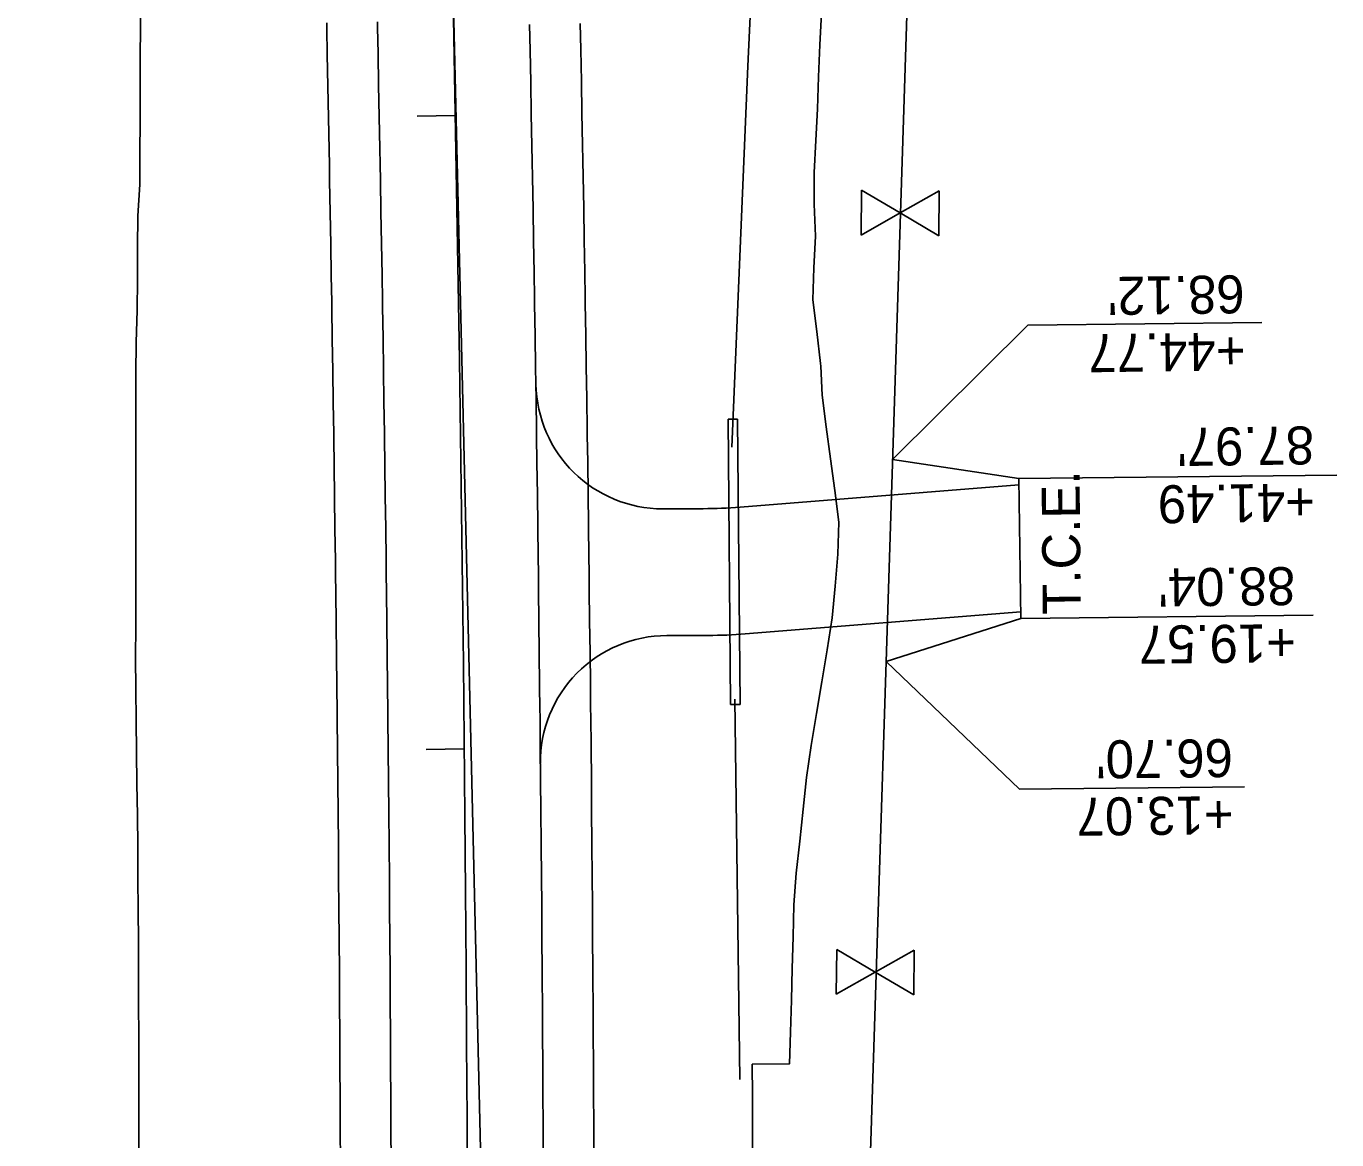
# Model space of a CAD drawing. Extents: x 634057 to 641016, y 287858 to 292331.
# Drawn here: x 634256.5 to 634463.2, y 290902.9 to 291078.6 of the extents above; entities that cross this region are included whole.
import ezdxf

# ---------------------------------------------------------------- set-up
doc = ezdxf.new("R2010")
doc.units = 0
for name, color, linetype in [('53', 7, 'Continuous'), ('PROPOSED SPECIAL DITCHES', 7, 'Continuous'), ('R_50 Horz Alg PC PI PT', 7, 'Continuous'), ('R_50 Horz Alg Ticks', 7, 'Continuous'), ('R_Drive', 7, 'Continuous'), ('R_Horz Alg', 7, 'Continuous'), ('R_Proposed Const Limits', 7, 'Continuous'), ('R_Proposed Road', 7, 'Continuous'), ('R_Proposed Shoulder', 7, 'Continuous'), ('R_ROW', 7, 'Continuous'), ('R_Water', 7, 'Continuous')]:
    doc.layers.add(name, color=color, linetype=linetype)

msp = doc.modelspace()

# ---------------------------------------------------------------- linework, layer by layer
at = {"layer": '53'}
for p, q in [((634463.23, 291007.76), (634413.05, 291007.22)), ((634459.5, 290985.67), (634413.39, 290985.14))]:
    msp.add_line(p, q, dxfattribs=at)
for points in [[(634414.48, 291031.42), (634393.15, 291010.25)], [(634451.39, 291031.86), (634414.5, 291031.42)], [(634392.13, 290978.35), (634413.15, 290958.19)], [(634413.15, 290958.19), (634448.69, 290958.58)]]:
    msp.add_lwpolyline(points, dxfattribs=at)
at = {"layer": 'PROPOSED SPECIAL DITCHES'}
for points in [[(634367.76, 291012.19), (634370.29, 291072.3), (634378.27, 291242.02), (634381.78, 291263.48)], [(634369.03, 290912.39), (634368.25, 290972.39)]]:
    msp.add_lwpolyline(points, dxfattribs=at)
at = {"layer": 'R_50 Horz Alg PC PI PT'}
msp.add_lwpolyline([(634341.05, 290353.77), (634322.94, 291121.85)], dxfattribs=at)
at = {"layer": 'R_50 Horz Alg Ticks'}
for points in [[(634318.15, 291064.43), (634324.15, 291064.54)], [(634319.57, 290964.49), (634325.57, 290964.55)]]:
    msp.add_lwpolyline(points, dxfattribs=at)
at = {"layer": 'R_Drive'}
for p, q in [((634369.09, 291002.71), (634413.06, 291006.24)), ((634356.93, 291002.45), (634363.26, 291002.47)), ((634369.91, 290982.71), (634413.38, 290986.2)), ((634357.53, 290982.45), (634364.09, 290982.47))]:
    msp.add_line(p, q, dxfattribs=at)
for centre, radius, start, end in [((634356.88, 291022.45), 20, 180.8408, 270.1318), ((634363.09, 291077.47), 75, 270.1318, 274.5873), ((634357.58, 290962.45), 20, 90.1318, 180.5616), ((634363.91, 291057.47), 75, 270.1318, 274.5873)]:
    msp.add_arc(centre, radius, start, end, dxfattribs=at)
at = {"layer": 'R_Horz Alg'}
msp.add_arc((622866.97, 290851.82), 11459.16, 353.678846, 1.350269, dxfattribs=at)
at = {"layer": 'R_Proposed Const Limits'}
for points in [[(634274.25, 290899.34), (634274.24, 290904.31), (634274.24, 290909.29), (634274.22, 290914.26), (634274.22, 290914.27), (634274.2, 290919.25), (634274.19, 290924.22), (634274.18, 290929.2), (634274.15, 290934.18), (634274.11, 290939.16), (634274.07, 290944.13), (634274.05, 290949.11), (634273.99, 290954.09), (634273.93, 290959.06), (634273.87, 290964.04), (634273.81, 290969.02), (634273.74, 290974), (634273.72, 290978.97), (634273.73, 290983.95), (634273.75, 290988.93), (634273.75, 290993.91), (634273.75, 290998.89), (634273.76, 291003.86), (634273.77, 291008.84), (634273.77, 291013.82), (634273.75, 291018.8), (634273.76, 291023.37), (634273.77, 291023.78), (634273.78, 291028.75), (634273.97, 291033.74), (634274, 291038.72), (634274.02, 291043.69), (634274.05, 291048.67), (634274.36, 291053.66), (634274.4, 291058.64), (634274.44, 291063.62), (634274.44, 291068.6), (634274.45, 291073.58), (634274.48, 291078.56), (634274.5, 291083.54)], [(634381.93, 291080.69), (634381.69, 291075.66), (634381.45, 291070.63), (634381.29, 291065.6), (634381.04, 291060.57), (634380.8, 291055.54), (634380.75, 291050.51), (634380.98, 291045.49), (634380.71, 291040.46), (634380.57, 291035.44), (634381.22, 291030.42), (634381.78, 291025.4), (634381.81, 291024.99), (634382.02, 291020.38), (634382.69, 291015.37), (634383.36, 291010.35), (634384.02, 291005.33), (634384.67, 291000.32), (634384.52, 290995.29), (634384.1, 290990.26), (634383.64, 290985.22), (634382.81, 290980.19), (634381.98, 290975.16), (634381.14, 290970.12), (634380.3, 290965.09), (634379.56, 290960.06), (634379.04, 290955.03), (634378.5, 290950), (634377.91, 290944.97), (634377.58, 290939.95), (634377.45, 290934.92), (634377.32, 290929.9), (634377.18, 290924.88), (634377.03, 290919.85), (634376.88, 290914.83), (634371.01, 290914.79)], [(634371.01, 290914.79), (634371.02, 290909.78), (634371.03, 290904.76), (634371.05, 290899.74)]]:
    msp.add_lwpolyline(points, dxfattribs=at)
at = {"layer": 'R_Proposed Road'}
for points in [[(634314.02, 290899.5), (634314, 290904.5), (634314, 290905.72), (634313.98, 290909.49), (634313.95, 290914.49), (634313.92, 290919.48), (634313.89, 290924.48), (634313.87, 290927.31), (634313.86, 290929.47), (634313.82, 290934.46), (634313.79, 290939.46), (634313.75, 290944.45), (634313.71, 290948.89), (634313.71, 290949.45), (634313.66, 290954.44), (634313.62, 290959.44), (634313.57, 290964.43), (634313.52, 290969.43), (634313.51, 290970.48), (634313.47, 290974.42), (634313.41, 290979.42), (634313.36, 290984.41), (634313.3, 290989.4), (634313.26, 290992.07), (634313.23, 290994.4), (634313.17, 290999.39), (634313.11, 291004.39), (634313.04, 291009.38), (634312.98, 291013.65), (634312.97, 291014.38), (634312.9, 291019.37), (634312.82, 291024.36), (634312.75, 291029.36), (634312.67, 291034.35), (634312.65, 291035.23), (634312.59, 291039.35), (634312.5, 291044.34), (634312.42, 291049.34), (634312.33, 291054.33), (634312.29, 291056.82), (634312.24, 291059.32), (634312.15, 291064.32), (634312.06, 291069.31), (634311.96, 291074.31), (634311.88, 291078.4), (634311.86, 291079.3)], [(634338.02, 290899.6), (634338, 290904.61), (634338, 290905.83), (634337.98, 290909.61), (634337.95, 290914.62), (634337.92, 290919.62), (634337.89, 290924.63), (634337.87, 290927.47), (634337.86, 290929.63), (634337.82, 290934.64), (634337.79, 290939.64), (634337.75, 290944.65), (634337.71, 290949.1), (634337.71, 290949.65), (634337.66, 290954.66), (634337.62, 290959.66), (634337.57, 290964.67), (634337.52, 290969.67), (634337.51, 290970.73), (634337.46, 290974.68), (634337.41, 290979.68), (634337.35, 290984.69), (634337.29, 290989.69), (634337.26, 290992.36), (634337.23, 290994.7), (634337.17, 290999.7), (634337.1, 291004.71), (634337.04, 291009.71), (634336.98, 291013.99), (634336.97, 291014.72), (634336.89, 291019.72), (634336.82, 291024.73), (634336.74, 291029.73), (634336.66, 291034.74), (634336.65, 291035.62), (634336.58, 291039.74), (634336.5, 291044.75), (634336.42, 291049.75), (634336.33, 291054.75), (634336.28, 291057.25), (634336.24, 291059.76), (634336.15, 291064.76), (634336.05, 291069.77), (634335.96, 291074.77), (634335.88, 291078.88)]]:
    msp.add_lwpolyline(points, dxfattribs=at)
at = {"layer": 'R_Proposed Shoulder'}
for points in [[(634306.02, 290899.47), (634306, 290904.46), (634306, 290905.68), (634305.98, 290909.45), (634305.95, 290914.44), (634305.92, 290919.43), (634305.89, 290924.42), (634305.87, 290927.25), (634305.86, 290929.42), (634305.82, 290934.41), (634305.79, 290939.4), (634305.75, 290944.39), (634305.71, 290948.83), (634305.71, 290949.38), (634305.66, 290954.37), (634305.62, 290959.36), (634305.57, 290964.35), (634305.52, 290969.34), (634305.51, 290970.4), (634305.47, 290974.34), (634305.41, 290979.33), (634305.36, 290984.32), (634305.3, 290989.31), (634305.26, 290991.97), (634305.24, 290994.3), (634305.17, 290999.29), (634305.11, 291004.28), (634305.04, 291009.27), (634304.98, 291013.54), (634304.97, 291014.26), (634304.9, 291019.25), (634304.82, 291024.24), (634304.75, 291029.24), (634304.67, 291034.23), (634304.65, 291035.11), (634304.59, 291039.22), (634304.51, 291044.21), (634304.42, 291049.2), (634304.33, 291054.19), (634304.29, 291056.68), (634304.24, 291059.18), (634304.15, 291064.17), (634304.06, 291069.16), (634303.96, 291074.15), (634303.88, 291078.24), (634303.86, 291079.14)], [(634346.02, 290899.64), (634346, 290904.64), (634346, 290905.87), (634345.98, 290909.65), (634345.95, 290914.66), (634345.92, 290919.67), (634345.89, 290924.68), (634345.87, 290927.52), (634345.86, 290929.69), (634345.82, 290934.7), (634345.79, 290939.7), (634345.75, 290944.71), (634345.71, 290949.16), (634345.71, 290949.72), (634345.66, 290954.73), (634345.62, 290959.74), (634345.57, 290964.75), (634345.52, 290969.76), (634345.51, 290970.81), (634345.46, 290974.76), (634345.41, 290979.77), (634345.35, 290984.78), (634345.29, 290989.79), (634345.26, 290992.46), (634345.23, 290994.8), (634345.17, 290999.81), (634345.1, 291004.81), (634345.04, 291009.82), (634344.98, 291014.1), (634344.97, 291014.83), (634344.89, 291019.84), (634344.82, 291024.85), (634344.74, 291029.86), (634344.66, 291034.86), (634344.65, 291035.75), (634344.58, 291039.87), (634344.5, 291044.88), (634344.41, 291049.89), (634344.33, 291054.9), (634344.28, 291057.39), (634344.24, 291059.9), (634344.14, 291064.91), (634344.05, 291069.92), (634343.95, 291074.93), (634343.87, 291079.04)]]:
    msp.add_lwpolyline(points, dxfattribs=at)
at = {"layer": 'R_ROW'}
for p, q in [((634388.2, 291045.66), (634388.26, 291052.73)), ((634388.26, 291052.73), (634394.35, 291049.15)), ((634394.35, 291049.15), (634400.5, 291052.63)), ((634400.5, 291052.63), (634400.44, 291045.56)), ((634394.35, 291049.15), (634388.2, 291045.66)), ((634400.44, 291045.56), (634394.35, 291049.15)), ((634384.27, 290925.84), (634384.33, 290932.91)), ((634384.33, 290932.91), (634390.42, 290929.33)), ((634390.42, 290929.33), (634396.57, 290932.81)), ((634396.57, 290932.81), (634396.51, 290925.74)), ((634390.42, 290929.33), (634384.27, 290925.84)), ((634396.51, 290925.74), (634390.42, 290929.33))]:
    msp.add_line(p, q, dxfattribs=at)
for points in [[(634385.92, 290784.2), (634404.17, 291355.03)], [(634392.13, 290978.35), (634413.39, 290985.14), (634413.05, 291007.22), (634393.15, 291010.25)]]:
    msp.add_lwpolyline(points, dxfattribs=at)
at = {"layer": 'R_Water'}
for points in [[(634367.2, 291016.58), (634368.7, 291016.59)], [(634367.2, 291016.58), (634367.6, 290971.57)], [(634368.7, 291016.59), (634369.1, 290971.59)], [(634367.6, 290971.57), (634369.1, 290971.59)]]:
    msp.add_lwpolyline(points, dxfattribs=at)

# ---------------------------------------------------------------- texts
at = {"layer": '53'}
for s, rotation, p in [("68.12'  ", 180.7875, (634448.64, 291039.33)), ('+44.77 ', 180.7875, (634448.77, 291030.33)), ("87.97'  ", 180.7711, (634459.61, 291015.48)), ('T.C.E.', 90.5225, (634422.85, 290985.77)), ('+41.49 ', 180.7711, (634459.73, 291006.48)), ("88.04'  ", 180.6615, (634456.63, 290993.27)), ('+19.57 ', 180.6615, (634456.74, 290984.27)), ("66.70'  ", 180.629, (634446.81, 290966.12)), ('+13.07 ', 180.629, (634446.91, 290957.12))]:
    msp.add_text(s, height=6, rotation=rotation, dxfattribs=at).set_placement(p)

doc.saveas('drawing.dxf')
